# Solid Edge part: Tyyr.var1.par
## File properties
Author: jaanm
Template: ansi metric part.par
Last saved by: jaanm
Revision: 11
Application: Solid Edge
Accuracy: 0,990
Face Style: Model Default
Coef. of Thermal Exp: 0.0
Thermal Conductivity: 0.0
Specific Heat: 0.0
Modulus of Elasticity: 0.0
Poisson's Ratio: 0.0
Yield Stress: 0.0
Ultimate Stress: 0.0
Elongation: 0.0
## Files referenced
..\Lendavkaru.asm
C:\Users\jaanm\Google Drive\Ained2016\3dmodel\Lendav käru\Telg.par
ru\Lendavkaru.asm
ru\Telg.par
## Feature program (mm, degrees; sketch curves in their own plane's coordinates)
sketch for "unnamed Protrusion 1" plane through (0, 0, 0) normal (0, -1, 0) x-axis (1, 0, 0)
  line (400, 50) -> (-400, 50)
  line (-400, 50) -> (-400, -50)
  line (-400, -50) -> (400, -50)
  line (400, -50) -> (400, 50)
extrude "unnamed Protrusion 1" add finite 100 along +normal
multibody boolean "unnamed MultibodyBoolean 1"
sketch for "ExtrudedProtrusion_2" plane through (-400, -50, 0) normal (-1, 0, 0) x-axis (0, 0, 1)
  line (-50, 50) -> (-50, 87.1222)
  line (50, 50) -> (-50, 87.1222)
  line (50, 50) -> (-50, 50)
extrude "ExtrudedProtrusion_2" add finite 800.8625 along -normal
sketch for "ExtrudedProtrusion_3" #1 plane through (0.4312, 18.5611, 0) normal (0, 0.937488, 0.348016) x-axis (1, 0, 0)
  line (-300.4312, -46.666) -> (-300.4312, 53.334)
  line (-300.4312, 53.334) -> (-400.4312, 53.334)
  line (-400.4312, 53.334) -> (-400.4312, -46.666)
  line (-400.4312, -46.666) -> (-300.4312, -46.666)
sketch for "ExtrudedProtrusion_3" #2 plane through (0.4312, 18.5611, 0) normal (0, 0.937488, 0.348016) x-axis (1, 0, 0)
  line (299.5688, -46.666) -> (299.5688, 53.334)
  line (299.5688, 53.334) -> (399.5688, 53.334)
  line (399.5688, 53.334) -> (399.5688, -46.666)
  line (399.5688, -46.666) -> (299.5688, -46.666)
extrude "ExtrudedProtrusion_3" add finite 400 along +normal
redefine surface "unnamed RedefineSurface 1"
sketch for "unnamed Protrusion 2" plane through (400, -50, 0) normal (1, 0, 0) x-axis (0, -1, 0)
  arc centre (-87.1222, -531.9752) radius 581.9752 from (-87.1222, 50) to (-503.4908, -125.3644) ccw
  line (-503.4908, -125.3644) -> (-503.4908, -157.3326)
  arc centre (-147.2534, -537.9849) radius 521.3457 from (-202.7676, -19.6033) to (-503.4908, -157.3326) ccw
  arc centre (-189.0843, -147.3753) radius 128.5026 from (-105.2335, -50) to (-202.7676, -19.6033) ccw
  arc centre (-77.6167, -17.9289) radius 42.323 from (-50, -50) to (-105.2335, -50) cw
  arc centre (-87.1222, -6.8903) radius 56.8903 from (-87.1222, 50) to (-50, -50) cw
extrude "unnamed Protrusion 2" add to key point along -normal
sketch for "ExtrudedCutout_1" plane through (0, 0, 0) normal (0, 0, 1) x-axis (1, 0, 0)
  arc centre (650, 453.4908) radius 350 from (300, 453.4908) to (1000, 453.4908) cw
extrude "ExtrudedCutout_1" cut finite 299.0749 along +normal
mirror "unnamed Mirror 1" about plane through (0, 0, 0) normal (1, 0, 0)
mirror "unnamed Mirror 2" about plane through (0, 0, 0) normal (1, 0, 0)
body pattern "unnamed BodyPattern 1"
pattern "unnamed Pattern 1"
body pattern "unnamed BodyPattern 2"
pattern "unnamed Pattern 2"
body pattern "unnamed BodyPattern 3"
mirror "unnamed Mirror 3" of "unnamed Protrusion 2" about plane through (0, 0, 0) normal (1, 0, 0)
pattern "unnamed Pattern 3"
extrude "unnamed Protrusion 3" add finite 100
sketch used by "ExtrudedProtrusion_6" plane through (350, 209.1386, 120.5243) normal (0, -0.348016, 0.937488) x-axis (0, -0.937488, -0.348016)
extrude "ExtrudedProtrusion_6" add finite 200 along -normal
sketch used by "ExtrudedProtrusion_7" plane through (350, 319.4938, -51.8454) normal (0, 0.348016, -0.937488) x-axis (-1, 0, 0)
extrude "ExtrudedProtrusion_7" add finite 350 along +normal
replace surface "unnamed ReplaceSurface 1"
mirror "unnamed Mirror 4" of "ExtrudedProtrusion_7", "ExtrudedProtrusion_6" about plane through (0, 0, 0) normal (1, 0, 0)
extrude "unnamed Protrusion 4" add finite 200
extrude "unnamed Protrusion 5" add finite 350
Other named dimensions: "SweptSurface_1": Scale_Start = 1; Scale_End = 1 | "SweptSurface_4": Scale_Start = 1; Scale_End = 1 | "OffsetSurface_1": Distance = 500 mm
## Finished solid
Body 1: sheet body, 1 face, 4 edges, 4 vertices.
  Faces by surface: cylinder 1
  Edges by curve: circle 2, line 2
Body 2: solid body, 12 faces, 28 edges, 20 vertices, 2 separate solids.
  Faces by surface: spline 10, plane 2
  Edges by curve: spline 12, curve on surface 6, line 6, circle 4
Body 3: solid body, 14 faces, 30 edges, 20 vertices, 2 separate solids.
  Faces by surface: plane 8, cylinder 6
  Edges by curve: line 14, ellipse 12, intersection 4
Body 4: sheet body, 1 face, 4 edges, 4 vertices.
  Faces by surface: plane 1
  Edges by curve: curve on surface 3, line 1
Body 5: solid body, 12 faces, 24 edges, 16 vertices, 2 separate solids.
  Faces by surface: plane 6, spline 6
  Edges by curve: line 10, curve on surface 6, spline 6, circle 2
Body 6: solid body, 149 faces, 192 edges, 54 vertices.
  Faces by surface: plane 74, cylinder 67, spline 4, torus 4
  Edges by curve: circle 132, intersection 28, line 28, curve on surface 4
Body 7: solid body, 42 faces, 90 edges, 52 vertices.
  Faces by surface: plane 27, cylinder 13, spline 2
  Edges by curve: line 60, circle 22, intersection 6, ellipse 2
Bounding box of the edges (mm; curved faces can reach further): 2287.838 x 1977.003 x 973.037, from (-1143.9188, -1165.7916, -550) to (1143.9188, 811.2111, 423.0365).
Cylindrical faces by radius (mm): R3.5 x14, R6.5 x14, R10 x20, R10.0415 x14, R15 x2, R15.9841 x2, R20 x2, R20.0196 x2, R25 x1, R42.323 x2, R45 x2, R50 x2, R350 x4, R521.3457 x2, R581.9752 x2, R1081.9752 x2
Toroidal faces (ring radius, tube radius in mm): R35 r10 x4
Planar faces by outward normal: +x 40, +y 6, +z 1, -x 38, -y 6, -z 1, oblique 25
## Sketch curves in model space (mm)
arc centre (650, 453.4908, 0) radius 350 from (300, 453.4908, 0) through (660.3717, 803.3371, 0) to (1000, 453.4908, 0)
line (300, 576.3171, 240.643) -> (300, 453.4908, 157.3326)
line (300, 570.0085, 220.5895) -> (300, 576.3171, 240.643)
line (300, 463.9208, 129.2363) -> (300, 570.0085, 220.5895)
arc centre (300, 453.4908, 141.3485) radius 15.9841 from (300, 453.4908, 125.3644) through (300, 459.0535, 126.3636) to (300, 463.9208, 129.2363)
line (300, 453.4908, 125.3644) -> (300, 453.4908, 157.3326)
line (1128.9188, 500.2352, 62.8401) -> (1128.9188, 588.9154, -116.4246)
arc centre (1023.4965, 500.2352, 62.8401) radius 105.4223 from (1023.4965, 453.4908, 157.3326) through (1100.1779, 468.1573, 127.6848) to (1128.9188, 500.2352, 62.8401)
line (1000, 453.4908, 157.3326) -> (1023.4965, 453.4908, 157.3326)
arc centre (1128.9188, 538.3945, -141.4167) radius 15 from (1143.6809, 540.7799, -140.2367) through (1128.4742, 524.9556, -148.0648) to (1114.1568, 540.7799, -140.2367)
line (1123.9982, 589.7105, -116.0313) -> (1114.1568, 540.7799, -140.2367)
arc centre (1128.9188, 588.9154, -116.4246) radius 5 from (1123.9982, 589.7105, -116.0313) through (1129.0669, 593.3951, -114.2086) to (1133.8395, 589.7105, -116.0313)
line (1133.8395, 589.7105, -116.0313) -> (1143.6809, 540.7799, -140.2367)
spline (1000, 248.5779, 24.0593) -> (1000, 359.2082, 59.0381) -> (1000, 453.4908, 125.3644)
arc centre (1000, 242.0551, 43.8519) radius 20.8398 from (1000, 236.6812, 63.9869) through (1000, 222.083, 37.9011) to (1000, 248.5779, 24.0593)
spline (1000, 453.4908, 157.3326) -> (1000, 355.7872, 86.5551) -> (1000, 236.6812, 63.9869)
line (1000, 453.4908, 157.3326) -> (1000, 453.4908, 125.3644)
arc centre (350, 189.8778, -99.9617) radius 50 from (300.4404, 196.0858, -97.6572) through (350, 143.0034, -117.3626) to (399.5596, 196.0858, -97.6572)
line (330.1567, 404.5841, -20.258) -> (300.4404, 196.0858, -97.6572)
arc centre (350, 402.0985, -21.1807) radius 20.0196 from (369.8433, 404.5841, -20.258) through (350, 420.8666, -14.2136) to (330.1567, 404.5841, -20.258)
line (369.8433, 404.5841, -20.258) -> (399.5596, 196.0858, -97.6572)
circle centre (350, 249.8905, 135.6523) radius 20
arc centre (400, 27.6167, 17.9289) radius 42.323 from (400, 0, 50) through (400, 27.6167, 60.2519) to (400, 55.2335, 50)
arc centre (400, 139.0843, 147.3753) radius 128.5026 from (400, 55.2335, 50) through (400, 100.85, 24.6926) to (400, 152.7676, 19.6033)
arc centre (400, 97.2534, 537.9849) radius 521.3457 from (400, 152.7676, 19.6033) through (400, 314.3414, 63.9869) to (400, 453.4908, 157.3326)
line (400, 453.4908, 125.3644) -> (400, 453.4908, 157.3326)
arc centre (400, 37.1222, 531.9752) radius 581.9752 from (400, 37.1222, -50) through (400, 263.0179, -4.3701) to (400, 453.4908, 125.3644)
arc centre (400, 37.1222, 6.8903) radius 56.8903 from (400, 37.1222, -50) through (400, -16.7751, -11.319) to (400, 0, 50)
line (-300, 2.3206, 43.7488) -> (-300, 37.1222, -50)
line (-300, 37.1222, -50) -> (-400, 37.1222, -50)
line (-400, 37.1222, -50) -> (-400, 2.3206, 43.7488)
line (-400, 2.3206, 43.7488) -> (-300, 2.3206, 43.7488)
line (300, 2.3206, 43.7488) -> (300, 37.1222, -50)
line (300, 37.1222, -50) -> (400, 37.1222, -50)
line (400, 37.1222, -50) -> (400, 2.3206, 43.7488)
line (400, 2.3206, 43.7488) -> (300, 2.3206, 43.7488)
line (-400, 0, -50) -> (-400, 37.1222, -50)
line (-400, 0, 50) -> (-400, 37.1222, -50)
line (-400, 0, 50) -> (-400, 0, -50)
line (400, 0, -50) -> (400, 0, 50)
line (400, 0, 50) -> (-400, 0, 50)
line (-400, 0, 50) -> (-400, 0, -50)
line (-400, 0, -50) -> (400, 0, -50)
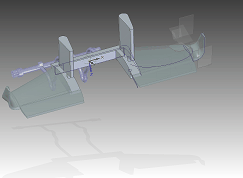
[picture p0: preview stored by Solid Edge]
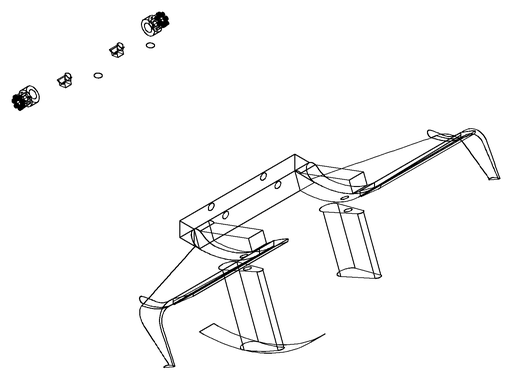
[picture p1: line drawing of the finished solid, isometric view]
